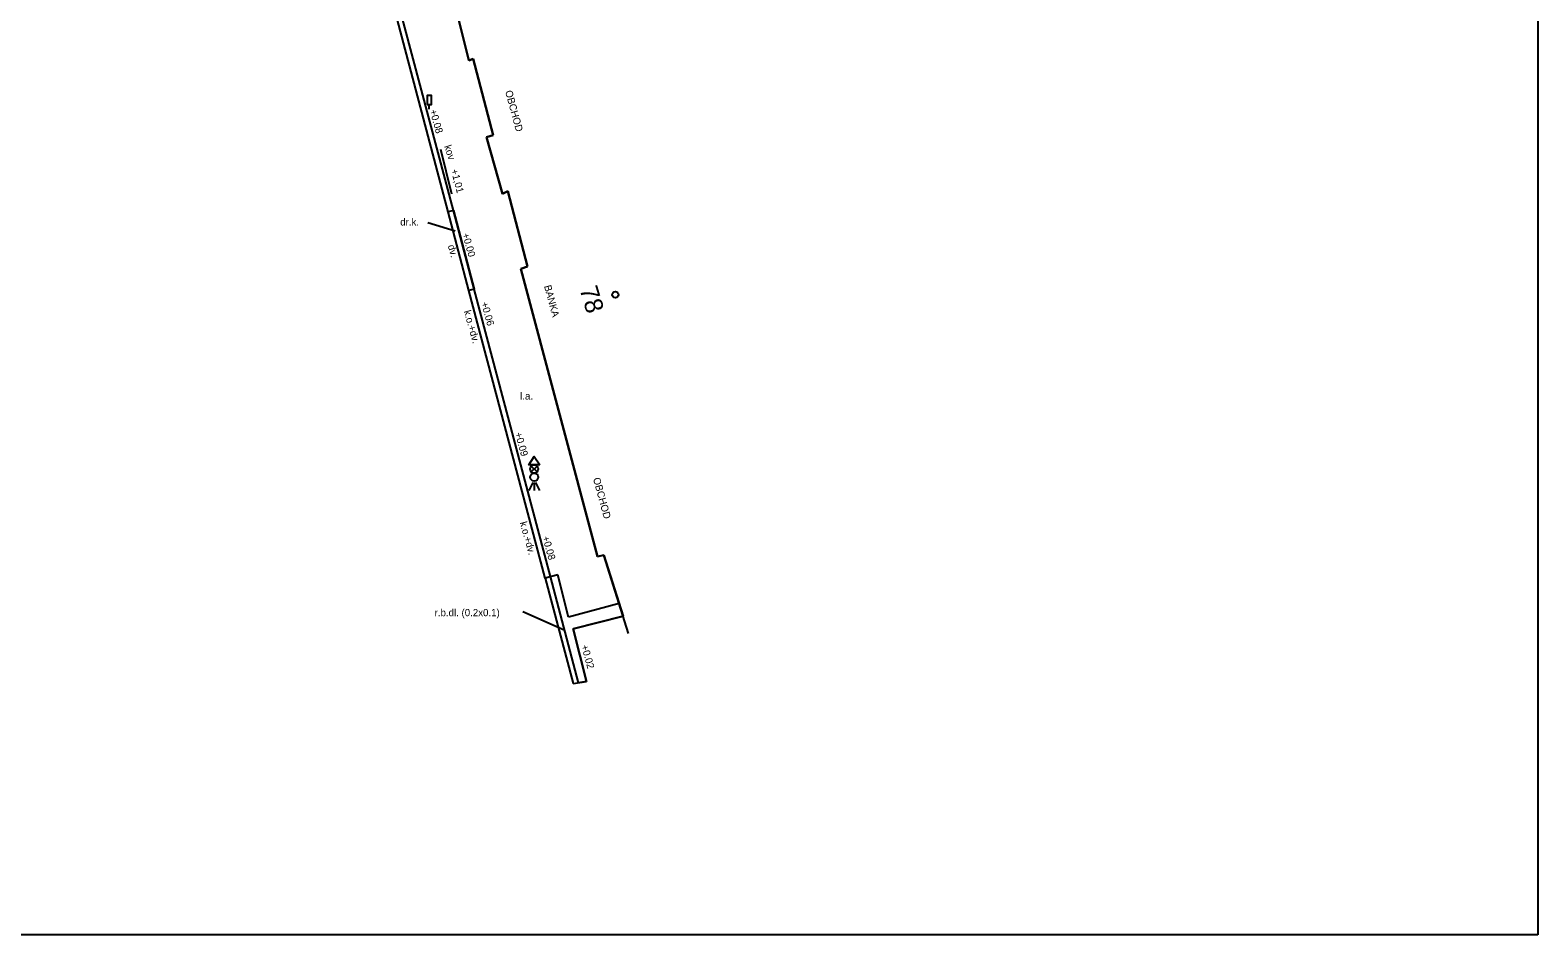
# Model space of a CAD drawing. Extents: x -598845 to -598697, y -1157541 to -1157331.
# Drawn here: x -598780.6 to -598697.2, y -1157540.8 to -1157490.8 of the extents above; entities that cross this region are included whole.
import ezdxf

# ---------------------------------------------------------------- set-up
doc = ezdxf.new("R2010")
doc.units = 0
for name, color, linetype in [('Vrstva 1', 7, 'Continuous'), ('Vrstva 15', 7, 'Continuous'), ('Vrstva 22', 7, 'Continuous'), ('Vrstva 4', 7, 'Continuous'), ('Vrstva 43', 7, 'Continuous'), ('Vrstva 44', 7, 'Continuous'), ('Vrstva 49', 7, 'Continuous'), ('Vrstva 50', 7, 'Continuous'), ('Vrstva 63', 7, 'Continuous'), ('Vrstva 7', 7, 'Continuous')]:
    doc.layers.add(name, color=color, linetype=linetype)

msp = doc.modelspace()

# ---------------------------------------------------------------- linework, layer by layer
at = {"layer": 'Vrstva 1'}
for p, q in [((-598697.222, -1157330.847), (-598697.223, -1157540.847)), ((-598697.223, -1157540.847), (-598845.222, -1157540.847))]:
    msp.add_line(p, q, dxfattribs=at)
at = {"layer": 'Vrstva 15'}
msp.add_line((-598758.52, -1157495.18), (-598758.52, -1157494.93), dxfattribs=at)
msp.add_lwpolyline([(-598758.645, -1157494.93), (-598758.395, -1157494.93), (-598758.395, -1157494.43), (-598758.645, -1157494.43)], close=True, dxfattribs=at)
msp.add_circle((-598748.23, -1157505.447), 0.175, dxfattribs=at)
at = {"layer": 'Vrstva 22'}
msp.add_line((-598757.27, -1157499.88), (-598757.88, -1157497.41), dxfattribs=at)
at = {"layer": 'Vrstva 4'}
for p, q in [((-598756.33, -1157492.495), (-598758.304, -1157484.635)), ((-598756.09, -1157492.4), (-598756.33, -1157492.495)), ((-598756.33, -1157492.495), (-598756.33, -1157492.495)), ((-598754.991, -1157496.622), (-598756.09, -1157492.4)), ((-598755.358, -1157496.724), (-598754.991, -1157496.622)), ((-598754.467, -1157499.862), (-598755.358, -1157496.724)), ((-598754.171, -1157499.724), (-598754.467, -1157499.862)), ((-598753.09, -1157503.893), (-598754.171, -1157499.724)), ((-598753.46, -1157504.02), (-598753.09, -1157503.893)), ((-598749.211, -1157519.931), (-598753.46, -1157504.02)), ((-598748.872, -1157519.85), (-598749.211, -1157519.931)), ((-598747.5, -1157524.18), (-598748.872, -1157519.85))]:
    msp.add_line(p, q, dxfattribs=at)
at = {"layer": 'Vrstva 44'}
for p, q in [((-598752.558, -1157514.922), (-598752.878, -1157515.242)), ((-598752.878, -1157514.922), (-598752.558, -1157515.242)), ((-598752.793, -1157515.832), (-598753.018, -1157516.282)), ((-598752.718, -1157515.832), (-598752.718, -1157516.282)), ((-598752.643, -1157515.832), (-598752.418, -1157516.282))]:
    msp.add_line(p, q, dxfattribs=at)
msp.add_lwpolyline([(-598752.414, -1157514.851), (-598753.016, -1157514.851), (-598752.717, -1157514.394)], close=True, dxfattribs=at)
for centre, radius in [((-598752.718, -1157515.082), 0.226), ((-598752.718, -1157515.532), 0.224)]:
    msp.add_circle(centre, radius, dxfattribs=at)
at = {"layer": 'Vrstva 49'}
for p, q in [((-598758.591, -1157501.449), (-598757.086, -1157501.906)), ((-598753.355, -1157522.974), (-598751.07, -1157523.976))]:
    msp.add_line(p, q, dxfattribs=at)
at = {"layer": 'Vrstva 63'}
for p, q in [((-598757.183, -1157500.793), (-598762.738, -1157479.8)), ((-598758.304, -1157484.635), (-598756.33, -1157492.495)), ((-598756.33, -1157492.495), (-598756.09, -1157492.4)), ((-598756.09, -1157492.4), (-598754.991, -1157496.622)), ((-598754.991, -1157496.622), (-598755.358, -1157496.724)), ((-598755.358, -1157496.724), (-598754.467, -1157499.862)), ((-598754.467, -1157499.862), (-598754.171, -1157499.724)), ((-598754.171, -1157499.724), (-598753.09, -1157503.893)), ((-598757.183, -1157500.793), (-598756.035, -1157505.13)), ((-598753.09, -1157503.893), (-598753.46, -1157504.02)), ((-598753.46, -1157504.02), (-598749.211, -1157519.931)), ((-598751.825, -1157521.037), (-598756.035, -1157505.13)), ((-598749.211, -1157519.931), (-598748.872, -1157519.85)), ((-598748.872, -1157519.85), (-598747.805, -1157523.217)), ((-598750.263, -1157526.901), (-598751.825, -1157521.037)), ((-598747.805, -1157523.217), (-598750.57, -1157523.92)), ((-598750.57, -1157523.92), (-598749.83, -1157526.83)), ((-598749.83, -1157526.83), (-598750.263, -1157526.901))]:
    msp.add_line(p, q, dxfattribs=at)
at = {"layer": 'Vrstva 7'}
for p, q in [((-598757.473, -1157500.87), (-598763.028, -1157479.877)), ((-598757.183, -1157500.793), (-598757.473, -1157500.87)), ((-598756.325, -1157505.207), (-598757.473, -1157500.87)), ((-598756.035, -1157505.13), (-598757.183, -1157500.793)), ((-598756.035, -1157505.13), (-598756.325, -1157505.207)), ((-598752.115, -1157521.114), (-598756.325, -1157505.207)), ((-598751.42, -1157520.93), (-598752.115, -1157521.114)), ((-598752.115, -1157521.114), (-598750.56, -1157526.95)), ((-598750.82, -1157523.27), (-598751.42, -1157520.93)), ((-598748.025, -1157522.524), (-598750.82, -1157523.27)), ((-598750.57, -1157523.92), (-598747.805, -1157523.217)), ((-598749.83, -1157526.83), (-598750.57, -1157523.92)), ((-598750.56, -1157526.95), (-598749.83, -1157526.83))]:
    msp.add_line(p, q, dxfattribs=at)

# ---------------------------------------------------------------- texts
at = {"layer": 'Vrstva 43'}
msp.add_text('78', height=1, rotation=286.54717, dxfattribs=at).set_placement((-598750.218, -1157505.128))
at = {"layer": 'Vrstva 49'}
for s, rotation, p in [('OBCHOD', 285.26118, (-598754.33, -1157494.202)), ('kov', 288.04305, (-598757.699, -1157497.236)), ('dv.', 285.59596, (-598757.501, -1157502.739)), ('BANKA', 285.26118, (-598752.179, -1157504.971)), ('k.o.+dv.', 285.59596, (-598756.612, -1157506.362)), ('OBCHOD', 285.26118, (-598749.47, -1157515.614)), ('k.o.+dv.', 285.59596, (-598753.521, -1157518.051))]:
    msp.add_text(s, height=0.4, rotation=rotation, dxfattribs=at).set_placement(p)
for s, p in [('dr.k.', (-598760.126, -1157501.618)), ('l.a.', (-598753.494, -1157511.245)), ('r.b.dl. (0.2x0.1)', (-598758.223, -1157523.225))]:
    msp.add_text(s, height=0.4, dxfattribs=at).set_placement(p)
at = {"layer": 'Vrstva 50'}
for s, rotation, p in [('+0.08', 285.6364, (-598758.503, -1157495.261)), ('+1,01', 284.72944, (-598757.329, -1157498.55)), ('+0.00', 285.6364, (-598756.704, -1157502.091)), ('+0.06', 285.6364, (-598755.664, -1157505.9)), ('+0.09', 285.6364, (-598753.792, -1157513.114)), ('+0.08', 285.6364, (-598752.277, -1157518.85)), ('+0.02', 285.6364, (-598750.126, -1157524.866))]:
    msp.add_text(s, height=0.4, rotation=rotation, dxfattribs=at).set_placement(p)

doc.saveas('drawing.dxf')
